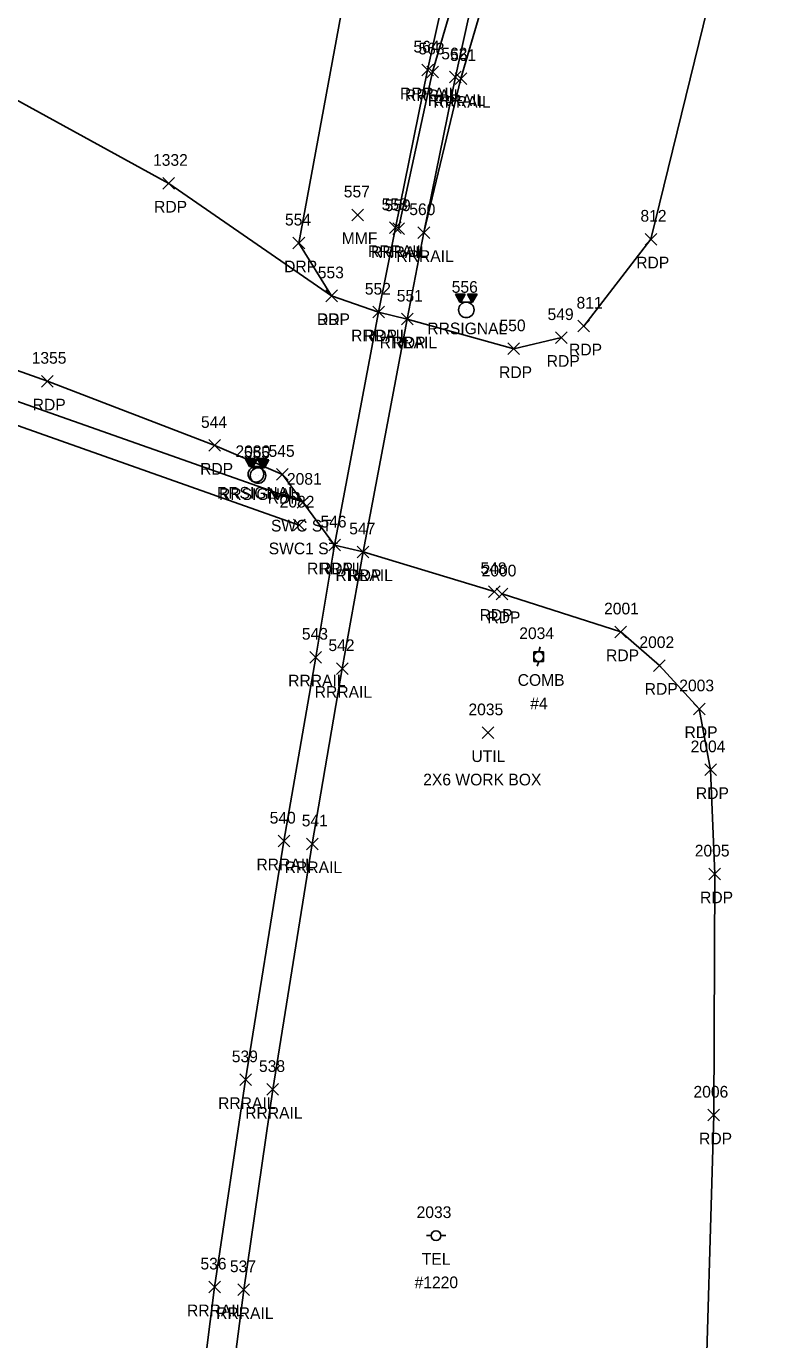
# Model space of a CAD drawing. Extents: x 1767353 to 1772625, y 740790 to 747702.
# Drawn here: x 1770148.4 to 1770273.7, y 741766 to 741990.7 of the extents above; entities that cross this region are included whole.
import ezdxf

# ---------------------------------------------------------------- set-up
doc = ezdxf.new("R2010")
doc.units = 0
for name, color, linetype in [('L_A', 7, 'Continuous'), ('L_I', 7, 'Continuous'), ('L_TIC', 7, 'Continuous'), ('P_A', 7, 'Continuous'), ('P_I', 7, 'Continuous'), ('P_TIC', 7, 'Continuous'), ('PET', 7, 'Continuous'), ('R_A', 7, 'Continuous'), ('R_I', 7, 'Continuous'), ('R_TIC', 7, 'Continuous'), ('RDP', 7, 'Continuous'), ('RR', 7, 'Continuous'), ('RSW', 7, 'Continuous'), ('TCSH', 7, 'Continuous'), ('U_A', 7, 'Continuous'), ('U_C', 7, 'Continuous'), ('U_I', 7, 'Continuous'), ('UDEFAULT', 7, 'Continuous'), ('UP', 7, 'Continuous')]:
    doc.layers.add(name, color=color, linetype=linetype)

msp = doc.modelspace()

# ---------------------------------------------------------------- linework, layer by layer
at = {"layer": 'L_TIC'}
for points in [[(1770204.07, 741957.43), (1770206.07, 741959.43)], [(1770206.07, 741957.43), (1770204.07, 741959.43)]]:
    msp.add_lwpolyline(points, dxfattribs=at)
at = {"layer": 'P_TIC'}
for points in [[(1770171.76, 741962.83), (1770173.76, 741964.83)], [(1770173.76, 741962.83), (1770171.76, 741964.83)], [(1770254.24, 741953.28), (1770256.24, 741955.28)], [(1770256.24, 741953.28), (1770254.24, 741955.28)], [(1770199.61, 741943.59), (1770201.61, 741945.59)], [(1770201.61, 741943.59), (1770199.61, 741945.59)], [(1770207.66, 741940.8), (1770209.66, 741942.8)], [(1770209.66, 741940.8), (1770207.66, 741942.8)], [(1770212.55, 741939.61), (1770214.55, 741941.61)], [(1770214.55, 741939.61), (1770212.55, 741941.61)], [(1770242.74, 741938.41), (1770244.74, 741940.41)], [(1770244.74, 741938.41), (1770242.74, 741940.41)], [(1770238.92, 741936.45), (1770240.92, 741938.45)], [(1770240.92, 741936.45), (1770238.92, 741938.45)], [(1770230.78, 741934.53), (1770232.78, 741936.53)], [(1770232.78, 741934.53), (1770230.78, 741936.53)], [(1770151.01, 741928.98), (1770153.01, 741930.98)], [(1770153.01, 741928.98), (1770151.01, 741930.98)], [(1770179.63, 741918), (1770181.63, 741920)], [(1770181.63, 741918), (1770179.63, 741920)], [(1770191.2, 741913.05), (1770193.2, 741915.05)], [(1770193.2, 741913.05), (1770191.2, 741915.05)], [(1770200.13, 741900.96), (1770202.13, 741902.96)], [(1770202.13, 741900.96), (1770200.13, 741902.96)], [(1770204.99, 741899.79), (1770206.99, 741901.79)], [(1770206.99, 741899.79), (1770204.99, 741901.79)], [(1770227.43, 741893), (1770229.43, 741895)], [(1770229.43, 741893), (1770227.43, 741895)], [(1770228.78, 741892.6), (1770230.78, 741894.6)], [(1770230.78, 741892.6), (1770228.78, 741894.6)], [(1770249.07, 741886.1), (1770251.07, 741888.1)], [(1770251.07, 741886.1), (1770249.07, 741888.1)], [(1770255.68, 741880.35), (1770257.68, 741882.35)], [(1770257.68, 741880.35), (1770255.68, 741882.35)], [(1770262.49, 741872.94), (1770264.49, 741874.94)], [(1770264.49, 741872.94), (1770262.49, 741874.94)], [(1770264.43, 741862.52), (1770266.43, 741864.52)], [(1770266.43, 741862.52), (1770264.43, 741864.52)], [(1770265.15, 741844.69), (1770267.15, 741846.69)], [(1770267.15, 741844.69), (1770265.15, 741846.69)], [(1770264.98, 741803.45), (1770266.98, 741805.45)], [(1770266.98, 741803.45), (1770264.98, 741805.45)]]:
    msp.add_lwpolyline(points, dxfattribs=at)
at = {"layer": 'PET'}
for points in [[(1770243.74, 741939.41), (1770255.24, 741954.28), (1770270.92, 742018.28), (1770293.62, 742096.86), (1770309.99, 742145.51), (1770335.13, 742217.35), (1770370.55, 742306.75), (1770390.86, 742357.46), (1770403.22, 742384.01), (1770418.01, 742412.4), (1770432.62, 742430.87), (1770448.87, 742440.9), (1770468.46, 742446.31), (1770490.36, 742448.75), (1770521.27, 742448.09), (1770553.51, 742444.86)], [(1770097.29, 741998.16), (1770140.08, 741981.73), (1770172.76, 741963.83)], [(1770172.76, 741963.83), (1770200.61, 741944.59)], [(1770086.33, 741898), (1770086.19, 741942.3), (1770087.55, 741952.88), (1770152.01, 741929.98)], [(1770239.92, 741937.45), (1770231.78, 741935.53), (1770213.55, 741940.61), (1770208.66, 741941.8), (1770200.61, 741944.59)], [(1770152.01, 741929.98), (1770180.63, 741919)], [(1770180.63, 741919), (1770192.2, 741914.05), (1770201.13, 741901.96), (1770205.99, 741900.79), (1770228.43, 741894)], [(1770229.78, 741893.6), (1770250.07, 741887.1), (1770256.68, 741881.35), (1770263.49, 741873.94), (1770265.43, 741863.52), (1770266.15, 741845.69), (1770265.98, 741804.45), (1770264.31, 741748.35), (1770263.25, 741697.67), (1770261.51, 741653.19), (1770259.69, 741610.34)]]:
    msp.add_lwpolyline(points, dxfattribs=at)
at = {"layer": 'R_TIC'}
for points in [[(1770216.02, 741982.21), (1770218.02, 741984.21)], [(1770218.02, 741982.21), (1770216.02, 741984.21)], [(1770216.88, 741981.89), (1770218.88, 741983.89)], [(1770218.88, 741981.89), (1770216.88, 741983.89)], [(1770220.78, 741981.04), (1770222.78, 741983.04)], [(1770222.78, 741981.04), (1770220.78, 741983.04)], [(1770221.72, 741980.76), (1770223.72, 741982.76)], [(1770223.72, 741980.76), (1770221.72, 741982.76)], [(1770210.54, 741955.24), (1770212.54, 741957.24)], [(1770212.54, 741955.24), (1770210.54, 741957.24)], [(1770211.06, 741955.08), (1770213.06, 741957.08)], [(1770213.06, 741955.08), (1770211.06, 741957.08)], [(1770215.39, 741954.4), (1770217.39, 741956.4)], [(1770217.39, 741954.4), (1770215.39, 741956.4)], [(1770215.39, 741954.4), (1770217.39, 741956.4)], [(1770217.39, 741954.4), (1770215.39, 741956.4)], [(1770194.01, 741952.62), (1770196.01, 741954.62)], [(1770196.01, 741952.62), (1770194.01, 741954.62)], [(1770199.61, 741943.59), (1770201.61, 741945.59)], [(1770201.61, 741943.59), (1770199.61, 741945.59)], [(1770207.66, 741940.8), (1770209.66, 741942.8)], [(1770209.66, 741940.8), (1770207.66, 741942.8)], [(1770212.55, 741939.61), (1770214.55, 741941.61)], [(1770214.55, 741939.61), (1770212.55, 741941.61)], [(1770194.74, 741908.28), (1770196.74, 741910.28)], [(1770196.74, 741908.28), (1770194.74, 741910.28)], [(1770194.07, 741904.38), (1770196.07, 741906.38)], [(1770196.07, 741904.38), (1770194.07, 741906.38)], [(1770200.13, 741900.96), (1770202.13, 741902.96)], [(1770202.13, 741900.96), (1770200.13, 741902.96)], [(1770204.99, 741899.79), (1770206.99, 741901.79)], [(1770206.99, 741899.79), (1770204.99, 741901.79)], [(1770196.89, 741881.78), (1770198.89, 741883.78)], [(1770198.89, 741881.78), (1770196.89, 741883.78)], [(1770201.43, 741879.83), (1770203.43, 741881.83)], [(1770203.43, 741879.83), (1770201.43, 741881.83)], [(1770191.47, 741850.32), (1770193.47, 741852.32)], [(1770193.47, 741850.32), (1770191.47, 741852.32)], [(1770196.31, 741849.84), (1770198.31, 741851.84)], [(1770198.31, 741849.84), (1770196.31, 741851.84)], [(1770184.91, 741809.5), (1770186.91, 741811.5)], [(1770186.91, 741809.5), (1770184.91, 741811.5)], [(1770189.55, 741807.84), (1770191.55, 741809.84)], [(1770191.55, 741807.84), (1770189.55, 741809.84)], [(1770179.59, 741774.05), (1770181.59, 741776.05)], [(1770181.59, 741774.05), (1770179.59, 741776.05)], [(1770184.58, 741773.59), (1770186.58, 741775.59)], [(1770186.58, 741773.59), (1770184.58, 741775.59)]]:
    msp.add_lwpolyline(points, dxfattribs=at)
at = {"layer": 'RDP'}
msp.add_lwpolyline([(1770200.61, 741944.59), (1770195.01, 741953.62), (1770209.39, 742031.53), (1770154.78, 742038.81), (1770134.02, 742040.78)], dxfattribs=at)
at = {"layer": 'RR'}
for points in [[(1770158.18, 741192.17), (1770156.33, 741234.55), (1770154.66, 741279.77), (1770153.5, 741326.69), (1770153.07, 741379.82), (1770153.42, 741422.94), (1770154.43, 741466.02), (1770156.03, 741508.16), (1770157.87, 741545.07), (1770160.69, 741586.39), (1770163.59, 741622.82), (1770166.84, 741658.9), (1770171.01, 741697.88), (1770175.49, 741734.8), (1770180.59, 741775.05), (1770185.91, 741810.5), (1770192.47, 741851.32), (1770197.89, 741882.78), (1770201.13, 741901.96), (1770208.66, 741941.8), (1770211.54, 741956.24), (1770217.02, 741983.21), (1770222.11, 742006.18)], [(1770163.08, 741192.31), (1770161.21, 741234.64), (1770159.62, 741280.6), (1770158.4, 741326.37), (1770158.03, 741379.87), (1770158.37, 741422.76), (1770159.48, 741466.41), (1770160.97, 741507.07), (1770162.92, 741544.79), (1770165.6, 741585.33), (1770168.59, 741623.26), (1770171.89, 741657.97), (1770175.98, 741697.29), (1770180.38, 741733.87), (1770185.58, 741774.59), (1770190.55, 741808.84), (1770197.31, 741850.84), (1770202.43, 741880.83), (1770205.99, 741900.79), (1770213.55, 741940.61), (1770216.39, 741955.4), (1770221.78, 741982.04), (1770226.9, 742005.14)], [(1770212.06, 741956.08), (1770217.88, 741982.89), (1770224.63, 742006.05)], [(1770216.39, 741955.4), (1770222.72, 741981.76), (1770229.32, 742004.36)]]:
    msp.add_lwpolyline(points, dxfattribs=at)
at = {"layer": 'RSW'}
for points in [[(1770195.74, 741909.28), (1770104.38, 741941.52), (1770086.66, 741947.17), (1770087.12, 741943.13)], [(1770195.07, 741905.38), (1770103.33, 741937.82), (1770087.12, 741943.13)]]:
    msp.add_lwpolyline(points, dxfattribs=at)
at = {"layer": 'TCSH'}
for p, q in [((1770223.47, 741944.85), (1770221.8, 741944.85)), ((1770221.8, 741944.85), (1770222.57, 741943.52)), ((1770222.7, 741943.52), (1770223.47, 741944.85)), ((1770225.5, 741944.85), (1770223.84, 741944.85)), ((1770223.84, 741944.85), (1770224.61, 741943.52)), ((1770224.73, 741943.52), (1770225.5, 741944.85)), ((1770224.73, 741943.52), (1770222.57, 741943.52)), ((1770223.65, 741942.19), (1770223.65, 741942.19)), ((1770187.49, 741916.74), (1770185.82, 741916.74)), ((1770185.82, 741916.74), (1770186.59, 741915.41)), ((1770187.85, 741916.51), (1770186.18, 741916.51)), ((1770186.18, 741916.51), (1770186.95, 741915.18)), ((1770188.76, 741915.41), (1770186.59, 741915.41)), ((1770186.72, 741915.41), (1770187.49, 741916.74)), ((1770189.11, 741915.18), (1770186.95, 741915.18)), ((1770187.08, 741915.18), (1770187.85, 741916.51)), ((1770189.53, 741916.74), (1770187.86, 741916.74)), ((1770187.86, 741916.74), (1770188.63, 741915.41)), ((1770189.88, 741916.51), (1770188.21, 741916.51)), ((1770188.21, 741916.51), (1770188.98, 741915.18)), ((1770188.76, 741915.41), (1770189.53, 741916.74)), ((1770189.11, 741915.18), (1770189.88, 741916.51)), ((1770187.67, 741914.07), (1770187.67, 741914.07)), ((1770188.03, 741913.85), (1770188.03, 741913.85))]:
    msp.add_line(p, q, dxfattribs=at)
for points in [[(1770221.85, 741944.78), (1770223.43, 741944.78)], [(1770221.92, 741944.64), (1770223.35, 741944.64)], [(1770222, 741944.51), (1770223.27, 741944.51)], [(1770222.08, 741944.38), (1770223.2, 741944.38)], [(1770222.16, 741944.24), (1770223.12, 741944.24)], [(1770222.23, 741944.11), (1770223.04, 741944.11)], [(1770223.87, 741944.81), (1770225.48, 741944.81)], [(1770223.94, 741944.67), (1770225.4, 741944.67)], [(1770224.02, 741944.54), (1770225.32, 741944.54)], [(1770224.1, 741944.41), (1770225.25, 741944.41)], [(1770224.17, 741944.27), (1770225.17, 741944.27)], [(1770224.25, 741944.14), (1770225.09, 741944.14)], [(1770222.31, 741943.98), (1770222.96, 741943.98)], [(1770222.39, 741943.84), (1770222.89, 741943.84)], [(1770222.46, 741943.71), (1770222.81, 741943.71)], [(1770222.54, 741943.58), (1770222.73, 741943.58)], [(1770224.33, 741944.01), (1770225.02, 741944.01)], [(1770224.4, 741943.87), (1770224.94, 741943.87)], [(1770224.48, 741943.74), (1770224.86, 741943.74)], [(1770224.56, 741943.61), (1770224.78, 741943.61)], [(1770185.87, 741916.66), (1770187.45, 741916.66)], [(1770185.95, 741916.53), (1770187.37, 741916.53)], [(1770186.02, 741916.4), (1770187.29, 741916.4)], [(1770186.1, 741916.26), (1770187.22, 741916.26)], [(1770186.18, 741916.13), (1770187.14, 741916.13)], [(1770186.22, 741916.44), (1770187.8, 741916.44)], [(1770186.25, 741916), (1770187.06, 741916)], [(1770186.3, 741916.3), (1770187.73, 741916.3)], [(1770186.33, 741915.86), (1770186.98, 741915.86)], [(1770186.38, 741916.17), (1770187.65, 741916.17)], [(1770186.41, 741915.73), (1770186.91, 741915.73)], [(1770186.46, 741916.04), (1770187.57, 741916.04)], [(1770186.48, 741915.6), (1770186.83, 741915.6)], [(1770186.53, 741915.9), (1770187.49, 741915.9)], [(1770186.56, 741915.46), (1770186.75, 741915.46)], [(1770186.61, 741915.77), (1770187.42, 741915.77)], [(1770186.69, 741915.64), (1770187.34, 741915.64)], [(1770186.76, 741915.5), (1770187.26, 741915.5)], [(1770186.84, 741915.37), (1770187.19, 741915.37)], [(1770186.92, 741915.24), (1770187.11, 741915.24)], [(1770187.89, 741916.69), (1770189.5, 741916.69)], [(1770187.96, 741916.56), (1770189.42, 741916.56)], [(1770188.04, 741916.43), (1770189.34, 741916.43)], [(1770188.12, 741916.29), (1770189.27, 741916.29)], [(1770188.19, 741916.16), (1770189.19, 741916.16)], [(1770188.24, 741916.46), (1770189.85, 741916.46)], [(1770188.27, 741916.03), (1770189.11, 741916.03)], [(1770188.32, 741916.33), (1770189.78, 741916.33)], [(1770188.35, 741915.89), (1770189.04, 741915.89)], [(1770188.4, 741916.2), (1770189.7, 741916.2)], [(1770188.43, 741915.76), (1770188.96, 741915.76)], [(1770188.47, 741916.06), (1770189.62, 741916.06)], [(1770188.5, 741915.63), (1770188.88, 741915.63)], [(1770188.55, 741915.93), (1770189.55, 741915.93)], [(1770188.58, 741915.49), (1770188.8, 741915.49)], [(1770188.63, 741915.8), (1770189.47, 741915.8)], [(1770188.7, 741915.66), (1770189.39, 741915.66)], [(1770188.78, 741915.53), (1770189.31, 741915.53)], [(1770188.86, 741915.4), (1770189.24, 741915.4)], [(1770188.94, 741915.26), (1770189.16, 741915.26)]]:
    msp.add_lwpolyline(points, dxfattribs=at)
for centre in [(1770223.65, 741942.19), (1770187.67, 741914.07), (1770188.03, 741913.85)]:
    msp.add_circle(centre, 1.33, dxfattribs=at)
at = {"layer": 'UDEFAULT'}
for points in [[(1770226.36, 741868.85), (1770228.36, 741870.85)], [(1770228.36, 741868.85), (1770226.36, 741870.85)]]:
    msp.add_lwpolyline(points, dxfattribs=at)
at = {"layer": 'UP'}
for p, q in [((1770235.22, 741882.05), (1770235.22, 741883.72)), ((1770235.22, 741883.72), (1770236.88, 741883.72)), ((1770236.3, 741884.55), (1770236.05, 741883.72)), ((1770236.88, 741883.72), (1770236.88, 741882.05)), ((1770236.88, 741882.05), (1770235.22, 741882.05)), ((1770235.8, 741881.22), (1770236.05, 741882.05)), ((1770236.05, 741882.88), (1770236.05, 741882.88)), ((1770216.82, 741783.85), (1770217.65, 741783.85)), ((1770218.48, 741783.85), (1770218.48, 741783.85)), ((1770220.15, 741783.85), (1770219.32, 741783.85)), ((1770219.32, 741783.85), (1770219.32, 741783.85)), ((1770220.15, 741783.85), (1770220.15, 741783.85))]:
    msp.add_line(p, q, dxfattribs=at)
for centre in [(1770236.05, 741882.88), (1770218.48, 741783.85)]:
    msp.add_circle(centre, 0.833, dxfattribs=at)

# ---------------------------------------------------------------- texts
at = {"layer": 'L_A'}
msp.add_text('MMF', height=2, dxfattribs=at).set_placement((1770202.35, 741953.43))
at = {"layer": 'L_I'}
msp.add_text('557', height=2, dxfattribs=at).set_placement((1770202.7, 741961.43))
at = {"layer": 'P_A'}
for p in [(1770170.25, 741958.83), (1770252.72, 741949.28), (1770198.1, 741939.59), (1770206.15, 741936.8), (1770211.04, 741935.61), (1770241.23, 741934.41), (1770237.41, 741932.45), (1770229.26, 741930.53), (1770149.49, 741924.98), (1770178.12, 741914), (1770189.68, 741909.05), (1770198.62, 741896.96), (1770203.48, 741895.79), (1770225.92, 741889), (1770227.26, 741888.6), (1770247.56, 741882.1), (1770254.17, 741876.35), (1770260.98, 741868.94), (1770262.92, 741858.52), (1770263.64, 741840.69), (1770263.47, 741799.45)]:
    msp.add_text('RDP', height=2, dxfattribs=at).set_placement(p)
at = {"layer": 'P_I'}
for s, p in [('1332', (1770170.07, 741966.83)), ('812', (1770253.44, 741957.28)), ('553', (1770198.25, 741947.59)), ('552', (1770206.3, 741944.8)), ('551', (1770211.76, 741943.61)), ('811', (1770242.51, 741942.41)), ('549', (1770237.55, 741940.45)), ('550', (1770229.33, 741938.53)), ('1355', (1770149.31, 741932.98)), ('544', (1770178.27, 741922)), ('545', (1770189.83, 741917.05)), ('546', (1770198.71, 741904.96)), ('547', (1770203.63, 741903.79)), ('548', (1770226.07, 741897)), ('2000', (1770226.27, 741896.6)), ('2001', (1770247.22, 741890.1)), ('2002', (1770253.26, 741884.35)), ('2003', (1770260.08, 741876.94)), ('2004', (1770262.02, 741866.52)), ('2005', (1770262.73, 741848.69)), ('2006', (1770262.51, 741807.45))]:
    msp.add_text(s, height=2, dxfattribs=at).set_placement(p)
at = {"layer": 'R_A'}
for s, p in [('RRRAIL', (1770212.31, 741978.21)), ('RRRAIL', (1770213.17, 741977.89)), ('RRRAIL', (1770217.07, 741977.04)), ('RRRAIL', (1770218.01, 741976.76)), ('RRRAIL', (1770206.83, 741951.24)), ('RRRAIL', (1770207.35, 741951.08)), ('RRRAIL', (1770211.69, 741950.4)), ('RRRAIL', (1770211.69, 741950.4)), ('DRP', (1770192.49, 741948.62)), ('DRP', (1770198.1, 741939.59)), ('RRSIGNAL', (1770216.98, 741938.01)), ('RRRAIL', (1770203.95, 741936.8)), ('RRRAIL', (1770208.84, 741935.61)), ('RRSIGNAL', (1770181, 741909.9)), ('RRSIGNAL', (1770181.36, 741909.67)), ('SWC ST', (1770190.24, 741904.28)), ('SWC1 ST', (1770189.85, 741900.38)), ('RRRAIL', (1770196.42, 741896.96)), ('RRRAIL', (1770201.28, 741895.79)), ('RRRAIL', (1770193.19, 741877.78)), ('RRRAIL', (1770197.73, 741875.83)), ('RRRAIL', (1770187.76, 741846.32)), ('RRRAIL', (1770192.6, 741845.84)), ('RRRAIL', (1770181.2, 741805.5)), ('RRRAIL', (1770185.84, 741803.84)), ('RRRAIL', (1770175.88, 741770.05)), ('RRRAIL', (1770180.87, 741769.59))]:
    msp.add_text(s, height=2, dxfattribs=at).set_placement(p)
at = {"layer": 'R_I'}
for s, p in [('564', (1770214.61, 741986.21)), ('563', (1770215.47, 741985.89)), ('562', (1770219.37, 741985.04)), ('561', (1770220.88, 741984.76)), ('558', (1770209.17, 741959.24)), ('559', (1770209.69, 741959.08)), ('560', (1770213.9, 741958.4)), ('560', (1770213.9, 741958.4)), ('554', (1770192.64, 741956.62)), ('553', (1770198.25, 741947.59)), ('552', (1770206.3, 741944.8)), ('556', (1770221.16, 741945.11)), ('551', (1770211.76, 741943.61)), ('2080', (1770184.17, 741917)), ('555', (1770185.59, 741916.77)), ('2081', (1770192.97, 741912.28)), ('2082', (1770191.73, 741908.38)), ('546', (1770198.71, 741904.96)), ('547', (1770203.63, 741903.79)), ('543', (1770195.53, 741885.78)), ('542', (1770200.07, 741883.83)), ('540', (1770190.02, 741854.32)), ('541', (1770195.51, 741853.84)), ('539', (1770183.54, 741813.5)), ('538', (1770188.19, 741811.84)), ('536', (1770178.18, 741778.05)), ('537', (1770183.22, 741777.59))]:
    msp.add_text(s, height=2, dxfattribs=at).set_placement(p)
at = {"layer": 'U_A'}
for s, p in [('COMB', (1770232.44, 741877.88)), ('UTIL', (1770224.53, 741864.85)), ('TEL', (1770216.04, 741778.85))]:
    msp.add_text(s, height=2, dxfattribs=at).set_placement(p)
at = {"layer": 'U_C'}
for s, p in [('#4', (1770234.59, 741873.88)), ('2X6 WORK BOX', (1770216.28, 741860.85)), ('#1220', (1770214.81, 741774.85))]:
    msp.add_text(s, height=2, dxfattribs=at).set_placement(p)
at = {"layer": 'U_I'}
for s, p in [('2034', (1770232.71, 741885.88)), ('2035', (1770224.02, 741872.85)), ('2033', (1770215.15, 741786.85))]:
    msp.add_text(s, height=2, dxfattribs=at).set_placement(p)

doc.saveas('drawing.dxf')
